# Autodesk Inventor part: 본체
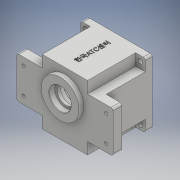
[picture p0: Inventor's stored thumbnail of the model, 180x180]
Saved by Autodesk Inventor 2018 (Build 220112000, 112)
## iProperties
Created: 2020-07
Part Number: 본체
Material: 일반
Document SubType Name: Modeling
Designer: admin
Density: 1 g/cm^3
Appearance: 기본값
Author: admin
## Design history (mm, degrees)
sketch "스케치1"
  geometry: L1 (47, -47)-(-47, -47); L2 (-47, -47)-(-47, 47); L3 (-47, 47)-(47, 47); L4 (47, 47)-(47, -47); L5 (47, -47)-(-47, 47); L6 (-47, -47)-(47, 47); 1 further point
  constraints: 12 end point, 2 midpoint, 2 parallel, 1 horizontal, 1 perpendicular
  dimensions: "d0" = 94 distance of L1.end L2.end; "d1" = 94 distance of L2.end L3.end
extrude "돌출1" new body sketch "스케치1" distance "d2" = 80; taper "d3" = 0 deg
sketch "스케치2"
  geometry: L1 (-98, 0)-(98, 0) reference; L2 (0, -65.8)-(0, 65.8) reference; L3 (-47, -47)-(47, -47) reference; L4 (47, -47)-(47, 47) reference; L5 (47, 47)-(-47, 47) reference; L6 (-47, 47)-(-47, -47) reference; L7 (-70, 30)-(70, 30); L8 (70, 30)-(70, -30); L9 (70, -30)-(-70, -30); L10 (-70, -30)-(-70, 30); 1 further point
  constraints: 8 end point, 2 parallel, 1 horizontal, 1 perpendicular, 2 other
  dimensions: "d4" = 140 distance of L7.start L7.end; "d5" = 60 distance of L7.end L8.end
extrude "돌출2" join sketch "스케치2" distance "d6" = 13; taper "d7" = 0 deg
sketch "스케치3"
  geometry: L1 (-47, -30)-(-47, -47) reference; L2 (-47, -47)-(47, -47) reference; L3 (47, -47)-(47, -30) reference; L4 (70, -30)-(47, -30) reference; L5 (70, 30)-(70, -30) reference; L6 (47, 30)-(70, 30) reference; L7 (47, 30)-(47, 47) reference; L8 (47, 47)-(-47, 47) reference; L9 (-47, 47)-(-47, 30) reference; L10 (-70, 30)-(-47, 30) reference; L11 (-70, -30)-(-70, 30) reference; L12 (-47, -30)-(-70, -30) reference; L13 (-98, 0)-(98, 0) reference; L14 (0, -65.8)-(0, 65.8) reference; L15 (-47, 47)-(-33, 47); L16 (-33, 47)-(-33, 30); L17 (-33, 30)-(-47, 30); L18 (-47, 30)-(-47, 47); L19 (47, 47)-(33, 47); L20 (47, 30)-(47, 47); L21 (33, 30)-(47, 30); L22 (33, 47)-(33, 30); L23 (-33, -47)-(-33, -30); L24 (-33, -30)-(-47, -30); L25 (-47, -47)-(-33, -47); L26 (-47, -30)-(-47, -47); L27 (33, -30)-(47, -30); L28 (47, -30)-(47, -47); L29 (33, -47)-(33, -30); L30 (47, -47)-(33, -47); 1 further point
  constraints: 32 end point, 12 symmetric about line, 2 parallel, 1 horizontal, 1 perpendicular
  dimensions: "d8" = 66 distance between parallel lines of L22 L16; "d9" = 60 distance between parallel lines of L27 L21
extrude "돌출3" cut sketch "스케치3" distance "d10" = 70; taper "d11" = 0 deg
sketch "스케치4"
  geometry: L1 (0, -65.8)-(0, 65.8) reference; L2 (-98, 0)-(98, 0) reference; L3 (-33, -30)-(-33, -47) reference; L4 (-33, -47)-(33, -47) reference; L5 (33, -47)-(33, -30) reference; L6 (70, -30)-(33, -30) reference; L7 (70, 30)-(70, -30) reference; L8 (70, 30)-(33, 30) reference; L9 (33, 30)-(33, 47) reference; L10 (33, 47)-(-33, 47) reference; L11 (-33, 47)-(-33, 30) reference; L12 (-70, 30)-(-33, 30) reference; L13 (-70, -30)-(-70, 30) reference; L14 (-70, -30)-(-33, -30) reference; C1 r 27.5 at (0, 11); 1 further point
  constraints: 1 centre point, 1 point on line
  dimensions: "d12" = 55 diameter of C1; "d13" = 11 distance from line of L2 C1.centre
extrude "돌출4" join sketch "스케치4" distance "d14" = 7; taper "d15" = 0 deg
sketch "스케치5"
  geometry: C1 r 43 at (0, 0); 1 further point
  constraints: 1 centre point, 1 coincident
  dimensions: "d16" = 86 diameter of C1
extrude "돌출5" cut sketch "스케치5" distance "d17" = 9; taper "d18" = 0 deg
sketch "스케치6" dims "d21" = 36
  geometry: L1 (-137.2, 0)-(137.2, 0) reference; L2 (0, 65.8)-(0, -65.8) reference; L3 (137.2, 0)-(-137.2, 0); A1 r 40 centre (0, 0) between (39.279, 7.559) and (-39.279, 7.559); A2 r 4 centre (36, 0) between (36.19, 3.995) and (36.19, -3.995); A3 r 3 centre (36.333, -6.992) between (39.279, -7.559) and (36.19, -3.995); A4 r 3 centre (36.333, 6.992) between (36.19, 3.995) and (39.279, 7.559); A5 r 4 centre (-36, 0) between (-36.19, -3.995) and (-36.19, 3.995); A6 r 3 centre (-36.333, -6.992) between (-36.19, -3.995) and (-39.279, -7.559); A7 r 3 centre (-36.333, 6.992) between (-39.279, 7.559) and (-36.19, 3.995); A8 r 40 centre (0, 0) between (-39.279, -7.559) and (39.279, -7.559); A9 r 40 centre (0, 0) between (39.279, 7.559) and (-39.279, 7.559); A10 r 40 centre (0, 0) between (-39.279, -7.559) and (39.279, -7.559); A11 r 40 centre (0, 0) between (-39.279, 7.559) and (-39.279, -7.559); 2 further points
  constraints: 22 point on circle, 12 symmetric about line, 11 centre point, 3 coincident, 2 end point, 2 horizontal alignment, 2 point on line, 2 tangent, 1 vertical, 8 other
  dimensions: "d19" = 80 diameter of A1; "d23" = 8 diameter of A2; "d24" = 3 radius of A3
extrude "돌출6" cut sketch "스케치6" distance "d26" = 62; taper "d27" = 0 deg
sketch "스케치7"
  geometry: C1 r 27.5 at (0, 0) reference; C2 r 16 at (0, 0); 1 further point
  constraints: 1 centre point, 1 coincident
  dimensions: "d28" = 32 diameter of C2
extrude "돌출7" cut sketch "스케치7" distance "d29" = 8.3; taper "d30" = 0 deg
chamfer "모따기1" distance "d31" = 0.8; stored, may be unused: second distance "d32" = 2, angle "d33" = 30 deg
sketch "스케치8"
  geometry: L1 (47, 47)-(-47, 47) reference; L2 (-47, 47)-(-47, -47) reference; L3 (-47, -47)-(47, -47) reference; L4 (47, -47)-(47, 47) reference; L5 (-47, 30)-(-47, -30) reference; L6 (-47, 30)-(-70, 30) reference; L7 (-70, 30)-(-70, -30) reference; L8 (-70, -30)-(-47, -30) reference; L9 (47, -30)-(47, 30) reference; L10 (47, -30)-(70, -30) reference; L11 (70, -30)-(70, 30) reference; L12 (70, 30)-(47, 30) reference; L13 (-98, 0)-(98, 0) reference; L14 (0, 65.8)-(0, -65.8) reference; C1 r 43 at (0, 0) reference; C2 r 43 at (0, 0) reference; A1 r 3 centre (36.333, -6.992) between (39.279, -7.559) and (36.19, -3.995) reference; A2 r 4 centre (36, 0) between (36.19, 3.995) and (36.19, -3.995) reference; A3 r 3 centre (36.333, 6.992) between (36.19, 3.995) and (39.279, 7.559) reference; A4 r 40 centre (0, 0) between (39.279, 7.559) and (-39.279, 7.559) reference; A5 r 3 centre (-36.333, 6.992) between (-39.279, 7.559) and (-36.19, 3.995) reference; A6 r 4 centre (-36, 0) between (-36.19, -3.995) and (-36.19, 3.995) reference; A7 r 3 centre (-36.333, -6.992) between (-36.19, -3.995) and (-39.279, -7.559) reference; A8 r 40 centre (0, 0) between (-39.279, -7.559) and (39.279, -7.559) reference; A9 r 21 centre (0, -11) between (-12.163, 6.119) and (12.163, 6.119); A10 r 15 centre (0, 20) between (11.584, 10.47) and (-11.584, 10.47); A11 r 3 centre (-13.901, 8.565) between (-12.163, 6.119) and (-11.584, 10.47); A12 r 3 centre (13.901, 8.565) between (11.584, 10.47) and (12.163, 6.119); 1 further point
  constraints: 8 point on circle, 4 centre point, 4 tangent, 2 point on line, 1 equal radius
  dimensions: "d34" = 21 radius of A9; "d35" = 11 distance from line of L13 A9.centre; "d36" = 15 radius of A10; "d37" = 20 distance from line of L13 A10.centre; "d38" = 3 radius of A11
extrude "돌출8" join sketch "스케치8" distance "d39" = 7; taper "d40" = 0 deg
sketch "스케치9"
  geometry: C1 r 17.5 at (0, -11); A1 r 3 centre (-13.901, 8.565) between (-12.163, 6.119) and (-11.584, 10.47) reference; A2 r 21 centre (0, -11) between (-12.163, 6.119) and (12.163, 6.119) reference; A3 r 3 centre (13.901, 8.565) between (11.584, 10.47) and (12.163, 6.119) reference; A4 r 15 centre (0, 20) between (11.584, 10.47) and (-11.584, 10.47) reference; 1 further point
  constraints: 1 centre point, 1 coincident
  dimensions: "d41" = 35 diameter of C1
extrude "돌출9" cut sketch "스케치9" distance "d42" = 10; taper "d43" = 0 deg
sketch "스케치10"
  geometry: C1 r 17.5 at (0, 0) reference; C2 r 12.5 at (0, 0); 1 further point
  constraints: 1 centre point, 1 coincident
  dimensions: "d44" = 25 diameter of C2
extrude "돌출10" cut sketch "스케치10" distance "d45" = 4.7; taper "d46" = 0 deg
sketch "스케치11"
  geometry: C1 r 17.5 at (0, -11) reference; C2 r 11 at (0, 20); A1 r 3 centre (-13.901, 8.565) between (-12.163, 6.119) and (-11.584, 10.47) reference; A2 r 21 centre (0, -11) between (-12.163, 6.119) and (12.163, 6.119) reference; A3 r 3 centre (13.901, 8.565) between (11.584, 10.47) and (12.163, 6.119) reference; A4 r 15 centre (0, 20) between (11.584, 10.47) and (-11.584, 10.47) reference; 1 further point
  constraints: 1 centre point, 1 coincident
  dimensions: "d47" = 22 diameter of C2
extrude "돌출11" cut sketch "스케치11" distance "d48" = 7; taper "d49" = 0 deg
sketch "스케치12"
  geometry: C1 r 11 at (0, 0) reference; C2 r 9.5 at (0, 0); 1 further point
  constraints: 1 centre point, 1 coincident
  dimensions: "d50" = 19 diameter of C2
extrude "돌출12" cut sketch "스케치12" distance "d51" = 3; taper "d52" = 0 deg
fillet "모깎기1" dims "d53" = 3
sketch "스케치13"
  geometry: L1 (-33, 30)-(-33, 47) reference; L2 (-33, 47)-(33, 47) reference; L3 (33, 47)-(33, 30) reference; L4 (70, 30)-(33, 30) reference; L5 (70, -30)-(70, 30) reference; L6 (70, -30)-(33, -30) reference; L7 (33, -30)-(33, -47) reference; L8 (33, -47)-(-33, -47) reference; L9 (-33, -47)-(-33, -30) reference; L10 (-70, -30)-(-33, -30) reference; L11 (-70, 30)-(-70, -30) reference; L12 (-70, 30)-(-33, 30) reference; L13 (0, 65.8)-(0, -65.8) reference; L14 (-98, 0)-(98, 0) reference; C1 r 27.5 at (0, -11) reference; 5 further points
  constraints: 2 horizontal alignment, 2 symmetric about line, 2 vertical alignment
  dimensions: "d54" = 120 distance of point (60, -19) point (-60, -19); "d55" = 38 distance of point (-60, 19) point (-60, -19)
hole "구멍1" sketch "스케치13" at (60, -19), (-60, -19), (-60, 19), (60, 19) diameter "d56" = 4.5; stored, may be unused: countersink angle "d60" = 90 deg, drill point angle "d62" = 0 deg; dims "d57" = 6, "d58" = 10, "d59" = 5, "d61" = 30
sketch "스케치14"
  geometry: L1 (47, -47)-(-47, -47) reference; L2 (-47, -47)-(-47, 47) reference; L3 (-47, 47)-(47, 47) reference; L4 (47, 47)-(47, -47) reference; L5 (-98, 0)-(98, 0) reference; L6 (0, -65.8)-(0, 65.8) reference; C1 r 43 at (0, 0) reference; C2 r 3.5 at (-40, 40); C3 r 3.5 at (40, 40); C4 r 3.5 at (-40, -40); C5 r 3.5 at (40, -40); 1 further point
  constraints: 4 centre point, 3 symmetric about line, 3 other
  dimensions: "d63" = 80 distance of C3.centre C2.centre; "d64" = 80 distance of C5.centre C3.centre; "d65" = 7 diameter of C3
extrude "돌출13" cut sketch "스케치14" extent not by distance; stored distance "d66" = 3; taper "d67" = 0 deg
sketch "스케치15"
  geometry: C1 r 43 at (0, 0) reference; A1 r 4 centre (36, 0) between (36.19, 3.995) and (36.19, -3.995) reference; A2 r 3 centre (36.333, -6.992) between (39.279, -7.559) and (36.19, -3.995) reference; A3 r 40 centre (0, 0) between (-39.279, -7.559) and (39.279, -7.559) reference; A4 r 3 centre (-36.333, -6.992) between (-36.19, -3.995) and (-39.279, -7.559) reference; A5 r 4 centre (-36, 0) between (-36.19, -3.995) and (-36.19, 3.995) reference; A6 r 3 centre (-36.333, 6.992) between (-39.279, 7.559) and (-36.19, 3.995) reference; A7 r 40 centre (0, 0) between (39.279, 7.559) and (-39.279, 7.559) reference; A8 r 3 centre (36.333, 6.992) between (36.19, 3.995) and (39.279, 7.559) reference; 3 further points
  constraints: 2 coincident
hole "구멍2" sketch "스케치15" at (36, 0), (-36, 0) diameter "d68" = 3.242; stored, may be unused: countersink angle "d72" = 90 deg, drill point angle "d74" = 118 deg; dims "d69" = 7, "d70" = 10, "d71" = 5, "d73" = 9
fillet "모깎기2" dims "d75" = 3
chamfer "모따기2" distance "d76" = 1; stored, may be unused: second distance "d77" = 2, angle "d78" = 30 deg
sketch "스케치16"
  geometry: L1 (33, -24.4)-(33, 97.4) reference; L2 (-11, 80)-(77, 80) reference; 2 further points
  constraints: 1 point on line, 1 other
  dimensions: "d79" = 40 distance from line of L2 point (33, 40)
feature "엠보싱1" sketch "스케치16" dims "d0" = 94, "d1" = 94, "d80" = 0.5, "d81" = 0
node "솔리드1"
node "투영된 루프1"
node "투영된 루프2"
node "투영된 루프3"
node "투영된 루프4"
node "투영된 루프5"
node "투영된 루프6"
node "투영된 루프7"
node "투영된 루프8"
node "투영된 루프9"
node "투영된 루프10"
node "투영된 루프11"
node "투영된 루프12"
node "투영된 루프13"
node "투영된 루프14"
node "투영된 루프15"
